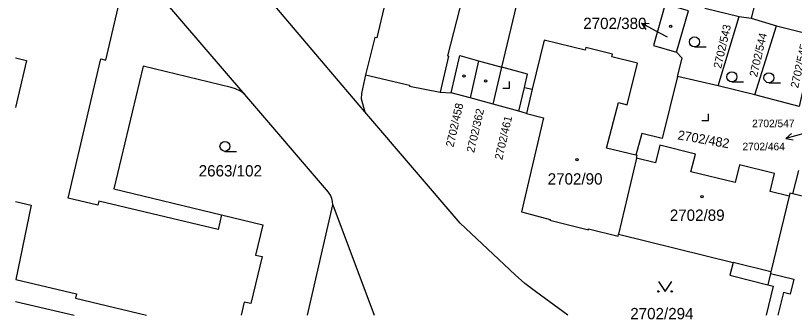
# Model space of a CAD drawing. Extents: x -496682 to -495907, y -1088575 to -1088018.
# Drawn here: x -496674.2 to -496557.4, y -1088570.1 to -1088524.5 of the extents above; entities that cross this region are included whole.
import ezdxf

# ---------------------------------------------------------------- set-up
doc = ezdxf.new("R2010")
doc.units = 0
for name, color, linetype in [('Hranice parcel', 7, 'Continuous'), ('Parcelní čísla', 7, 'Continuous'), ('Pop  PČ popisy', 7, 'Continuous'), ('Vnitřní kresba', 7, 'Continuous'), ('Značky budov', 7, 'Continuous'), ('Značky kultur', 7, 'Continuous')]:
    doc.layers.add(name, color=color, linetype=linetype)

msp = doc.modelspace()

# ---------------------------------------------------------------- linework, layer by layer
at = {"layer": 'Hranice parcel'}
for p, q in [((-496560.68, -1088512.06), (-496563.91, -1088524.85)), ((-496639.82, -1088536.3), (-496657.68, -1088515.47)), ((-496601.3, -1088532.22), (-496597.58, -1088516.58)), ((-496570.83, -1088523.36), (-496565.69, -1088524.64)), ((-496575.1, -1088529.97), (-496573.29, -1088523.79)), ((-496568.87, -1088535.04), (-496565.69, -1088524.64)), ((-496565.69, -1088524.64), (-496563.91, -1088524.85)), ((-496563.91, -1088524.85), (-496560.1, -1088526.02)), ((-496563.36, -1088536.35), (-496560.1, -1088526.02)), ((-496604.78, -1088531.26), (-496606.06, -1088536.81)), ((-496604.78, -1088531.26), (-496601.3, -1088532.22)), ((-496602.58, -1088537.75), (-496601.3, -1088532.22)), ((-496568.87, -1088535.04), (-496574.95, -1088533.64)), ((-496563.36, -1088536.35), (-496568.87, -1088535.04)), ((-496627.27, -1088550.98), (-496639.82, -1088536.3)), ((-496606.06, -1088536.81), (-496608.87, -1088536.05)), ((-496602.58, -1088537.75), (-496606.06, -1088536.81)), ((-496598.73, -1088538.84), (-496602.58, -1088537.75)), ((-496597.6, -1088539.16), (-496598.73, -1088538.84)), ((-496581.09, -1088545.9), (-496583.78, -1088557.29)), ((-496557.65, -1088551.23), (-496556.76, -1088547.74)), ((-496630.45, -1088569.45), (-496626.65, -1088552.9)), ((-496626.65, -1088552.9), (-496620.42, -1088569.45))]:
    msp.add_line(p, q, dxfattribs=at)
for points in [[(-496621.83, -1088538.93), (-496627.8, -1088531.94), (-496637.3, -1088520.68), (-496644.5, -1088512.3)], [(-496619.55, -1088518.48), (-496620.39, -1088522.17), (-496618.8, -1088522.54), (-496620.02, -1088527.84), (-496620.32, -1088527.76), (-496621.75, -1088533.36)], [(-496573.29, -1088523.79), (-496576.78, -1088522.78), (-496578.57, -1088528.99), (-496575.1, -1088529.97)], [(-496560.1, -1088526.02), (-496554.29, -1088527.46), (-496556.58, -1088537.69)], [(-496581.19, -1088545.41), (-496585.6, -1088544.35), (-496583.81, -1088537.52), (-496582.49, -1088537.85), (-496580.94, -1088531.64), (-496584.78, -1088530.69), (-496584.67, -1088530.25), (-496588.68, -1088529.26), (-496588.78, -1088529.68), (-496594.93, -1088528.15), (-496596.72, -1088535.54), (-496597.6, -1088539.16)], [(-496608.87, -1088536.05), (-496607.61, -1088530.48), (-496604.78, -1088531.26)], [(-496574.95, -1088533.64), (-496574.26, -1088530.86), (-496575.1, -1088529.97)], [(-496641.88, -1088535.27), (-496655.05, -1088532.06), (-496659.48, -1088550.5), (-496643.3, -1088554.38), (-496637.13, -1088555.87), (-496638.22, -1088560.45), (-496637.25, -1088560.61), (-496638.93, -1088567.68), (-496639.91, -1088567.46), (-496640.39, -1088569.45)], [(-496598.73, -1088538.84), (-496597.9, -1088535.25), (-496597.44, -1088533.28), (-496601.3, -1088532.22)], [(-496621.75, -1088533.36), (-496622.32, -1088536.19), (-496622.36, -1088536.99), (-496621.83, -1088538.93)], [(-496621.75, -1088533.36), (-496615.11, -1088534.91), (-496615.15, -1088535.05), (-496610.53, -1088535.95), (-496608.87, -1088536.05)], [(-496574.95, -1088533.64), (-496577.24, -1088542.91), (-496580.28, -1088542.18), (-496581.19, -1088545.41)], [(-496639.82, -1088536.3), (-496640.39, -1088535.89), (-496640.58, -1088535.77), (-496641.21, -1088535.48), (-496641.88, -1088535.27)], [(-496556.58, -1088537.69), (-496556.68, -1088538.12), (-496563.36, -1088536.35)], [(-496591.37, -1088569.45), (-496596.26, -1088565.89), (-496597.82, -1088564.67), (-496599.31, -1088563.38), (-496607.53, -1088555.63), (-496621.83, -1088538.93)], [(-496597.6, -1088539.16), (-496595.05, -1088539.8), (-496598.34, -1088553.91), (-496594.06, -1088555.06), (-496594.1, -1088555.19), (-496588.31, -1088556.62), (-496588.28, -1088556.49), (-496583.85, -1088557.58), (-496583.78, -1088557.29)], [(-496558.21, -1088551.57), (-496561.07, -1088550.86), (-496560.39, -1088548.19), (-496565.66, -1088546.9), (-496566.32, -1088549.55), (-496572.95, -1088547.91), (-496572.27, -1088545.25), (-496577.59, -1088543.93), (-496578.25, -1088546.6), (-496581.09, -1088545.9)], [(-496581.09, -1088545.9), (-496580.98, -1088545.46), (-496581.19, -1088545.41)], [(-496626.65, -1088552.9), (-496626.68, -1088552.36), (-496626.77, -1088551.94), (-496626.98, -1088551.44), (-496627.27, -1088550.98)], [(-496558.21, -1088551.57), (-496560.94, -1088562.93), (-496560.99, -1088563.18), (-496561.39, -1088564.87)], [(-496557.65, -1088551.23), (-496558.1, -1088551.12), (-496558.21, -1088551.57)], [(-496545.5, -1088569.45), (-496545.94, -1088569.34), (-496542.39, -1088555.02), (-496557.65, -1088551.23)], [(-496583.78, -1088557.29), (-496566.62, -1088561.53), (-496567.09, -1088563.44), (-496561.39, -1088564.87)], [(-496561.39, -1088564.87), (-496560.6, -1088565.07), (-496561.63, -1088569.45)], [(-496674.2, -1088567.37), (-496665.44, -1088569.45)]]:
    msp.add_lwpolyline(points, dxfattribs=at)
at = {"layer": 'Pop  PČ popisy'}
for p, q in [((-496577.69, -1088527.05), (-496580.34, -1088525.64)), ((-496580.34, -1088525.64), (-496579.22, -1088525.67)), ((-496580.34, -1088525.64), (-496579.69, -1088526.55)), ((-496576.45, -1088527.7), (-496577.69, -1088527.05)), ((-496555.81, -1088542.14), (-496558.71, -1088542.92)), ((-496558.71, -1088542.92), (-496557.87, -1088542.17)), ((-496558.71, -1088542.92), (-496557.61, -1088543.14))]:
    msp.add_line(p, q, dxfattribs=at)
at = {"layer": 'Vnitřní kresba'}
for p, q in [((-496605.65, -1088515.77), (-496609.45, -1088530.51)), ((-496660.69, -1088531.17), (-496658.07, -1088520.03)), ((-496609.3, -1088530.55), (-496610.53, -1088535.95)), ((-496609.45, -1088530.51), (-496609.3, -1088530.55)), ((-496674.2, -1088530.83), (-496672.54, -1088531.23)), ((-496672.54, -1088531.23), (-496674.2, -1088538.29)), ((-496666.34, -1088551.87), (-496661.44, -1088530.99)), ((-496661.44, -1088530.99), (-496660.69, -1088531.17)), ((-496597.9, -1088535.25), (-496596.72, -1088535.54)), ((-496674.2, -1088552.36), (-496671.86, -1088552.91)), ((-496661.88, -1088552.92), (-496666.34, -1088551.87)), ((-496661.74, -1088552.35), (-496661.88, -1088552.92)), ((-496643.82, -1088556.57), (-496661.74, -1088552.35)), ((-496671.86, -1088552.91), (-496674.15, -1088564.06)), ((-496643.3, -1088554.38), (-496643.82, -1088556.57)), ((-496560.94, -1088562.93), (-496566.62, -1088561.53)), ((-496560.99, -1088563.18), (-496557.51, -1088564.04)), ((-496674.15, -1088564.06), (-496665.08, -1088566.24)), ((-496557.51, -1088564.04), (-496558.07, -1088566.28)), ((-496665.08, -1088566.24), (-496665.2, -1088566.88)), ((-496559.04, -1088566.04), (-496559.88, -1088569.45)), ((-496558.07, -1088566.28), (-496559.04, -1088566.04)), ((-496665.2, -1088566.88), (-496654.57, -1088569.45))]:
    msp.add_line(p, q, dxfattribs=at)
at = {"layer": 'Značky budov'}
for centre in [(-496575.97, -1088526.08), (-496606.94, -1088533.54), (-496603.72, -1088534.29), (-496590.02, -1088546.11), (-496571.25, -1088551.66)]:
    msp.add_circle(centre, 0.175, dxfattribs=at)
at = {"layer": 'Značky kultur'}
for p, q in [((-496572.4, -1088529.18), (-496570.65, -1088529.18)), ((-496600.14, -1088535.35), (-496600.14, -1088534.35)), ((-496566.79, -1088534.42), (-496565.04, -1088534.42)), ((-496561.24, -1088534.56), (-496559.49, -1088534.56)), ((-496601.14, -1088535.35), (-496600.14, -1088535.35)), ((-496570.3, -1088540.24), (-496570.3, -1088539.24)), ((-496571.3, -1088540.24), (-496570.3, -1088540.24)), ((-496642.8, -1088544.85), (-496641.05, -1088544.85))]:
    msp.add_line(p, q, dxfattribs=at)
msp.add_lwpolyline([(-496577.82, -1088564.36), (-496576.82, -1088565.86), (-496575.82, -1088564.36)], dxfattribs=at)
for centre, radius in [((-496572.4, -1088528.43), 0.75), ((-496566.79, -1088533.67), 0.75), ((-496561.24, -1088533.81), 0.75), ((-496642.8, -1088544.1), 0.75), ((-496577.82, -1088565.86), 0.1), ((-496575.82, -1088565.86), 0.1)]:
    msp.add_circle(centre, radius, dxfattribs=at)

# ---------------------------------------------------------------- texts
at = {"layer": 'Parcelní čísla'}
for s, height, p in [('2702/380', 1.7, (-496589.08, -1088526.5)), ('2702/547', 1.139, (-496563.76, -1088541.23)), ('2702/464', 1.139, (-496565.2, -1088544.69)), ('2663/102', 1.7, (-496646.74, -1088548.62)), ('2702/90', 1.7, (-496594.41, -1088549.84)), ('2702/89', 1.7, (-496576.1, -1088555.28)), ('2702/294', 1.7, (-496582.03, -1088570.05))]:
    msp.add_text(s, height=height, dxfattribs=at).set_placement(p)
for s, height, rotation, p in [('2702/543', 1.2, 77, (-496568.41, -1088532.5)), ('2702/544', 1.2, 77, (-496563.02, -1088533.77)), ('2702/545', 1.2, 77, (-496556.86, -1088535.43)), ('2702/458', 1.2, 77, (-496608.55, -1088544.3)), ('2702/362', 1.2, 77, (-496605.44, -1088545.13)), ('2702/461', 1.2, 77, (-496601.23, -1088546.21)), ('2702/482', 1.401, 350, (-496575, -1088543.04))]:
    msp.add_text(s, height=height, rotation=rotation, dxfattribs=at).set_placement(p)

doc.saveas('drawing.dxf')
